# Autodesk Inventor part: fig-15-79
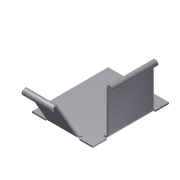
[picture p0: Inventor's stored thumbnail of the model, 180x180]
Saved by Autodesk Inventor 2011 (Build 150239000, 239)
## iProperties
Shininess: 77.0
Angle Display Precision: 2
Document Length Units: 11269
Document Angle Units: 11279
Document Time Units: 11290
Document Mass Units: 11283
Document Length Units Precision: 3
Document Angle Units Precision: 2
Compacted: True
Created: 2002-04
Part Number: fig-15-79
Document SubType Name: Sheet Metal
Density: 1 g/cm^3
Sheet Metal Rule: Default
Density: 0.0
Volumn: 0.0
Area: 0.0
PropertySet Name: Model Information
Control State: 0
Master: False
Checked Out: False
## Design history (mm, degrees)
node "Face1"
  sketch "Sketch1"
    geometry: L1 (-17.882, 11.882)-(2.118, 11.882); L2 (2.118, 11.882)-(2.118, -13.176); L3 (2.118, -13.176)-(-17.882, -13.176); L4 (-17.882, -13.176)-(-17.882, 11.882)
    constraints: 8 end point, 2 parallel, 1 horizontal, 1 perpendicular
    dimensions: "d17" = 20 distance of L2.end L3.end
node "Flange2"
node "Flange3"
feature "Hem8" dims "d82" = 0.5 (= BendReliefWidth), "d83" = 0.25 (= BendReliefDepth), "d84" = 1 (= MinimumRemnant), "d85" = 0.5 (= BendRadius), "d102" = 190 deg, "d103" = 0.5 (= BendRadius), "d104" = 0.5 (= d103), "SeamGap" = 0.01, "Thickness" = 0.5
feature "Hem9" dims "d89" = 0.5 (= BendReliefWidth), "d90" = 0.25 (= BendReliefDepth), "d91" = 1 (= MinimumRemnant), "d92" = 0.5 (= BendRadius), "d105" = 190 deg, "d106" = 0.5 (= BendRadius), "d107" = 0.5 (= d106), "SeamGap" = 0.01, "Thickness" = 0.5
body "Solid1"
face "Plate1" dims "Thickness" = 0.5
sketch "Sketch3"
  geometry: L1 (5, 0)-(20, 0); L2 (20, 0)-(20, 15); L3 (20, 15)-(5, 15); L4 (5, 15)-(5, 0)
  constraints: 8 end point
face "Plate3" dims "d6" = 15, "d7" = 90 deg, "d8" = 0.5 (= BendRadius), "d18" = 5, "d19" = 15, "Thickness" = 0.5, "MinimumRemnant" = 1 (= 2 x Thickness), "BendReliefWidth" = 0.5 (= Thickness)
bend "Bend2" dims "d6" = 15, "d7" = 90 deg, "d8" = 0.5 (= BendRadius), "d56" = 0.5 (= BendReliefWidth), "d57" = 0.25 (= BendReliefDepth), "d58" = 1 (= MinimumRemnant), "SeamGap" = 0.01, "Thickness" = 0.5, "MinimumRemnant" = 1 (= 2 x Thickness), "BendReliefWidth" = 0.5 (= Thickness), "TransitionRadius" = 0.5 (= BendRadius)
sketch "Sketch6"
  geometry: L1 (15, 0)-(5, 0); L2 (5, 0)-(5, 15); L3 (5, 15)-(15, 15); L4 (15, 15)-(15, 0)
  constraints: 8 end point
face "Plate4" dims "d20" = 5, "d21" = 10, "d23" = 15, "d24" = 60 deg, "d25" = 0.5 (= BendRadius), "Thickness" = 0.5, "MinimumRemnant" = 1 (= 2 x Thickness), "BendReliefWidth" = 0.5 (= Thickness)
bend "Bend3" dims "d22" = 0.5 (= BendRadius), "d23" = 15, "d24" = 60 deg, "d25" = 0.5 (= BendRadius), "d59" = 0.5 (= BendReliefWidth), "d60" = 0.25 (= BendReliefDepth), "d61" = 1 (= MinimumRemnant), "SeamGap" = 0.01, "Thickness" = 0.5, "MinimumRemnant" = 1 (= 2 x Thickness), "BendReliefWidth" = 0.5 (= Thickness)
sketch "Sketch12"
  geometry: L1 (0.433, 0.25)-(0, 0); L2 (-0.816, -0.571)-(-1.199, -0.893); A1 r 0.5 centre (-0.433, -0.25) between (0, 0) and (-0.816, -0.571); A2 r 1 centre (-0.433, -0.25) between (0.433, 0.25) and (-1.199, -0.893); 2 further points
  constraints: 4 end point, 4 point on circle
sketch "Sketch13"
  geometry: L1 (0.5, 0)-(0, 0); L2 (-0.992, -0.087)-(-1.485, -0.174); A1 r 0.5 centre (-0.5, 0) between (0, 0) and (-0.992, -0.087); A2 r 1 centre (-0.5, 0) between (0.5, 0) and (-1.485, -0.174); 2 further points
  constraints: 4 end point, 4 point on circle
other parameters: "BendRadius" = 0.5 (= Thickness), "BendReliefDepth" = 0.25 (= 0.5 x Thickness), "CornerReliefSize" = 2 (= 4 x Thickness), "d0" = 0.5 (= BendRadius), "d5" = 0.5 (= BendRadius), "d26" = 0.5 (= BendRadius), "d30" = 0.5 (= BendRadius), "JacobiRadiusSize" = 0.5 (= Thickness), "GapSize" = 0.5 (= Thickness)
